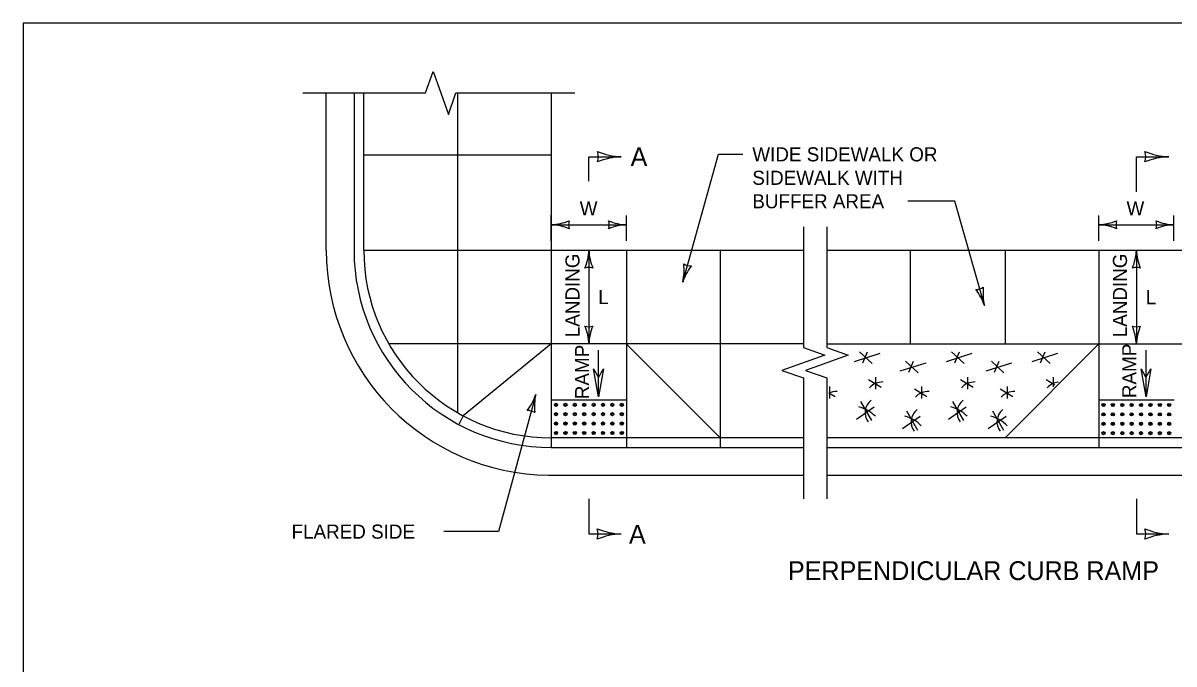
# Model space of a CAD drawing. Extents: x 49991.4 to 50021, y 49987.6 to 50011.4.
# Drawn here: x 50000.336 to 50005.241, y 50008.532 to 50011.263 of the extents above; entities that cross this region are included whole.
import ezdxf

# ---------------------------------------------------------------- set-up
doc = ezdxf.new("R2010")
doc.units = 0
for name, color, linetype in [('Level 1', 7, 'Continuous'), ('Level 2', 7, 'Continuous'), ('Level 3', 7, 'Continuous'), ('Level 6', 7, 'Continuous')]:
    doc.layers.add(name, color=color, linetype=linetype)

msp = doc.modelspace()

# ---------------------------------------------------------------- linework, layer by layer
at = {"layer": 'Level 1'}
for p, q in [((50001.6282, 50010.295), (50001.6282, 50010.9648)), ((50001.7464, 50010.9648), (50001.7464, 50010.2948)), ((50001.7878, 50010.2948), (50001.7878, 50010.9648)), ((50002.1877, 50010.9648), (50002.1877, 50009.6025)), ((50002.587, 50010.9648), (50002.587, 50009.4542)), ((50002.587, 50010.6998), (50001.7878, 50010.6997)), ((50001.7878, 50010.2949), (50003.6615, 50010.2949)), ((50002.9074, 50010.2949), (50002.9075, 50009.4542)), ((50003.3067, 50010.2949), (50003.3066, 50009.4542)), ((50003.7611, 50010.2949), (50007.0343, 50010.2946)), ((50004.1159, 50010.2948), (50004.116, 50009.8954)), ((50004.521, 50010.2948), (50004.5209, 50009.8954)), ((50004.9203, 50010.2948), (50004.9203, 50009.4542)), ((50003.6615, 50009.8954), (50001.8948, 50009.8954)), ((50002.587, 50009.8954), (50002.212, 50009.589)), ((50002.9075, 50009.8952), (50003.3066, 50009.4956)), ((50003.7611, 50009.8955), (50007.0343, 50009.8953)), ((50004.5207, 50009.4956), (50004.9203, 50009.8954)), ((50003.8786, 50009.821), (50003.9881, 50009.8556)), ((50003.9546, 50009.8129), (50003.9008, 50009.8616)), ((50003.9144, 50009.815), (50003.9345, 50009.8616)), ((50004.1504, 50009.7729), (50004.0967, 50009.8216)), ((50004.1102, 50009.775), (50004.1303, 50009.8216)), ((50004.2706, 50009.821), (50004.3801, 50009.8556)), ((50004.3466, 50009.8129), (50004.2928, 50009.8616)), ((50004.3064, 50009.815), (50004.3265, 50009.8616)), ((50004.5162, 50009.7729), (50004.4624, 50009.8216)), ((50004.4759, 50009.775), (50004.4961, 50009.8216)), ((50004.6363, 50009.821), (50004.7459, 50009.8556)), ((50004.7124, 50009.8129), (50004.6586, 50009.8616)), ((50004.6721, 50009.815), (50004.6923, 50009.8616)), ((50004.0744, 50009.781), (50004.1839, 50009.8156)), ((50004.4401, 50009.781), (50004.5497, 50009.8156)), ((50003.9387, 50009.7437), (50003.9923, 50009.7112)), ((50003.9699, 50009.7031), (50003.9699, 50009.7539)), ((50004.3307, 50009.7437), (50004.3843, 50009.7112)), ((50004.3619, 50009.7031), (50004.3619, 50009.7539)), ((50004.6965, 50009.7437), (50004.7329, 50009.7216)), ((50004.7276, 50009.7131), (50004.7276, 50009.7539)), ((50003.7697, 50009.6873), (50003.7961, 50009.6712)), ((50003.7737, 50009.6631), (50003.7737, 50009.7139)), ((50004.1345, 50009.7037), (50004.1881, 50009.6712)), ((50004.1657, 50009.6631), (50004.1657, 50009.7139)), ((50004.5003, 50009.7037), (50004.5539, 50009.6712)), ((50004.5315, 50009.6631), (50004.5315, 50009.7139)), ((50002.9075, 50009.6556), (50002.587, 50009.6556)), ((50003.8875, 50009.575), (50003.9635, 50009.6278)), ((50003.9053, 50009.6501), (50003.9523, 50009.5688)), ((50004.2795, 50009.575), (50004.3555, 50009.6278)), ((50004.2973, 50009.6501), (50004.3443, 50009.5688)), ((50005.2408, 50009.6556), (50004.9203, 50009.6556)), ((50002.212, 50009.589), (50002.1927, 50009.5526)), ((50004.0833, 50009.535), (50004.1594, 50009.5878)), ((50004.1011, 50009.6101), (50004.1481, 50009.5288)), ((50004.4491, 50009.535), (50004.5251, 50009.5878)), ((50004.4669, 50009.6101), (50004.5139, 50009.5288)), ((50003.6615, 50009.4956), (50002.587, 50009.4956)), ((50007.0343, 50009.4956), (50003.7611, 50009.4956)), ((50002.587, 50009.4542), (50003.6615, 50009.4542)), ((50003.7611, 50009.4542), (50007.0343, 50009.4542)), ((50002.575, 50009.336), (50003.6615, 50009.336)), ((50003.7611, 50009.336), (50007.0343, 50009.3357))]:
    msp.add_line(p, q, dxfattribs=at)
msp.add_lwpolyline([(50008.6146, 50011.2628), (50000.3356, 50011.2628), (50000.3356, 50000.0624), (50008.6146, 50000.0624)], close=True, dxfattribs=at)
for centre, radius in [((50002.6073, 50009.6363), 0.00675), ((50002.6073, 50009.6363), 0.00375), ((50002.6473, 50009.6363), 0.00675), ((50002.6473, 50009.6363), 0.00375), ((50002.6873, 50009.6363), 0.00675), ((50002.6873, 50009.6363), 0.00375), ((50002.7273, 50009.6363), 0.00675), ((50002.7273, 50009.6363), 0.00375), ((50002.7673, 50009.6363), 0.00675), ((50002.7673, 50009.6363), 0.00375), ((50002.8073, 50009.6363), 0.00675), ((50002.8073, 50009.6363), 0.00375), ((50002.8473, 50009.6363), 0.00675), ((50002.8473, 50009.6363), 0.00375), ((50002.8873, 50009.6363), 0.00675), ((50002.8873, 50009.6363), 0.00375), ((50004.9403, 50009.6355), 0.00675), ((50004.9403, 50009.6355), 0.00375), ((50004.9803, 50009.6355), 0.00675), ((50004.9803, 50009.6355), 0.00375), ((50005.0203, 50009.6355), 0.00675), ((50005.0203, 50009.6355), 0.00375), ((50005.0603, 50009.6355), 0.00675), ((50005.0603, 50009.6355), 0.00375), ((50005.1003, 50009.6355), 0.00675), ((50005.1003, 50009.6355), 0.00375), ((50005.1403, 50009.6355), 0.00675), ((50005.1403, 50009.6355), 0.00375), ((50005.1803, 50009.6355), 0.00675), ((50005.1803, 50009.6355), 0.00375), ((50005.2203, 50009.6355), 0.00675), ((50005.2203, 50009.6355), 0.00375), ((50002.6073, 50009.5963), 0.00675), ((50002.6073, 50009.5963), 0.00375), ((50002.6473, 50009.5963), 0.00675), ((50002.6473, 50009.5963), 0.00375), ((50002.6873, 50009.5963), 0.00675), ((50002.6873, 50009.5963), 0.00375), ((50002.7273, 50009.5963), 0.00675), ((50002.7273, 50009.5963), 0.00375), ((50002.7673, 50009.5963), 0.00675), ((50002.7673, 50009.5963), 0.00375), ((50002.8073, 50009.5963), 0.00675), ((50002.8073, 50009.5963), 0.00375), ((50002.8473, 50009.5963), 0.00675), ((50002.8473, 50009.5963), 0.00375), ((50002.8873, 50009.5963), 0.00675), ((50002.8873, 50009.5963), 0.00375), ((50004.9403, 50009.5955), 0.00675), ((50004.9403, 50009.5955), 0.00375), ((50004.9803, 50009.5955), 0.00675), ((50004.9803, 50009.5955), 0.00375), ((50005.0203, 50009.5955), 0.00675), ((50005.0203, 50009.5955), 0.00375), ((50005.0603, 50009.5955), 0.00675), ((50005.0603, 50009.5955), 0.00375), ((50005.1003, 50009.5955), 0.00675), ((50005.1003, 50009.5955), 0.00375), ((50005.1403, 50009.5955), 0.00675), ((50005.1403, 50009.5955), 0.00375), ((50005.1803, 50009.5955), 0.00675), ((50005.1803, 50009.5955), 0.00375), ((50005.2203, 50009.5955), 0.00675), ((50005.2203, 50009.5955), 0.00375), ((50002.6073, 50009.5563), 0.00675), ((50002.6073, 50009.5563), 0.00375), ((50002.6473, 50009.5563), 0.00675), ((50002.6473, 50009.5563), 0.00375), ((50002.6873, 50009.5563), 0.00675), ((50002.6873, 50009.5563), 0.00375), ((50002.7273, 50009.5563), 0.00675), ((50002.7273, 50009.5563), 0.00375), ((50002.7673, 50009.5563), 0.00675), ((50002.7673, 50009.5563), 0.00375), ((50002.8073, 50009.5563), 0.00675), ((50002.8073, 50009.5563), 0.00375), ((50002.8473, 50009.5563), 0.00675), ((50002.8473, 50009.5563), 0.00375), ((50002.8873, 50009.5563), 0.00675), ((50002.8873, 50009.5563), 0.00375), ((50004.9403, 50009.5555), 0.00675), ((50004.9403, 50009.5555), 0.00375), ((50004.9803, 50009.5555), 0.00675), ((50004.9803, 50009.5555), 0.00375), ((50005.0203, 50009.5555), 0.00675), ((50005.0203, 50009.5555), 0.00375), ((50005.0603, 50009.5555), 0.00675), ((50005.0603, 50009.5555), 0.00375), ((50005.1003, 50009.5555), 0.00675), ((50005.1003, 50009.5555), 0.00375), ((50005.1403, 50009.5555), 0.00675), ((50005.1403, 50009.5555), 0.00375), ((50005.1803, 50009.5555), 0.00675), ((50005.1803, 50009.5555), 0.00375), ((50005.2203, 50009.5555), 0.00675), ((50005.2203, 50009.5555), 0.00375), ((50002.6073, 50009.5163), 0.00675), ((50002.6073, 50009.5163), 0.00375), ((50002.6473, 50009.5163), 0.00675), ((50002.6473, 50009.5163), 0.00375), ((50002.6873, 50009.5163), 0.00675), ((50002.6873, 50009.5163), 0.00375), ((50002.7273, 50009.5163), 0.00675), ((50002.7273, 50009.5163), 0.00375), ((50002.7673, 50009.5163), 0.00675), ((50002.7673, 50009.5163), 0.00375), ((50002.8073, 50009.5163), 0.00675), ((50002.8073, 50009.5163), 0.00375), ((50002.8473, 50009.5163), 0.00675), ((50002.8473, 50009.5163), 0.00375), ((50002.8873, 50009.5163), 0.00675), ((50002.8873, 50009.5163), 0.00375), ((50004.9403, 50009.5155), 0.00675), ((50004.9403, 50009.5155), 0.00375), ((50004.9803, 50009.5155), 0.00675), ((50004.9803, 50009.5155), 0.00375), ((50005.0203, 50009.5155), 0.00675), ((50005.0203, 50009.5155), 0.00375), ((50005.0603, 50009.5155), 0.00675), ((50005.0603, 50009.5155), 0.00375), ((50005.1003, 50009.5155), 0.00675), ((50005.1003, 50009.5155), 0.00375), ((50005.1403, 50009.5155), 0.00675), ((50005.1403, 50009.5155), 0.00375), ((50005.1803, 50009.5155), 0.00675), ((50005.1803, 50009.5155), 0.00375), ((50005.2203, 50009.5155), 0.00675), ((50005.2203, 50009.5155), 0.00375)]:
    msp.add_circle(centre, radius, dxfattribs=at)
for centre, radius, start, end in [((50002.587, 50010.2947), 0.9588, 179.9835, 269.2811), ((50002.587, 50010.2948), 0.8406, 180, 270), ((50002.587, 50010.2948), 0.7992, 180, 270)]:
    msp.add_arc(centre, radius, start, end, dxfattribs=at)
for centre, major_axis, start_param, end_param in [((50004.0013, 50009.6641), (-0.0764, 0), 4.712389, 5.577205), ((50004.3933, 50009.6641), (-0.0764, 0), 4.712389, 5.577205), ((50004.7591, 50009.6641), (-0.0764, 0), 4.850702, 5.577205), ((50003.8051, 50009.6241), (-0.0764, 0), 4.712389, 5.191885), ((50004.1971, 50009.6241), (-0.0764, 0), 4.712389, 5.577205), ((50004.5629, 50009.6241), (-0.0764, 0), 4.712389, 5.577205), ((50003.8599, 50009.5017), (0.1432, 0), 0.715682, 1.301104), ((50004.0031, 50009.6034), (-0.0787, 0), 5.450961, 6.875887), ((50004.2519, 50009.5017), (0.1432, 0), 0.715682, 1.301104), ((50004.3951, 50009.6034), (-0.0787, 0), 5.450961, 6.875887), ((50004.0557, 50009.4617), (0.1432, 0), 0.715682, 1.301104), ((50004.1989, 50009.5634), (-0.0787, 0), 5.450961, 6.875887), ((50004.4215, 50009.4617), (0.1432, 0), 0.715682, 1.301104), ((50004.5647, 50009.5634), (-0.0787, 0), 5.450961, 6.875887)]:
    msp.add_ellipse(centre, major_axis=major_axis, ratio=0.909091, start_param=start_param, end_param=end_param, dxfattribs=at)
at = {"layer": 'Level 3'}
for p, q in [((50003.1472, 50010.1589), (50003.2993, 50010.7034)), ((50003.2993, 50010.7034), (50003.4037, 50010.7034)), ((50004.3072, 50010.5034), (50004.1058, 50010.5034)), ((50004.4327, 50010.0591), (50004.3072, 50010.5034)), ((50002.587, 50010.3347), (50002.587, 50010.4437)), ((50002.9074, 50010.3349), (50002.9074, 50010.4434)), ((50004.9203, 50010.3348), (50004.9203, 50010.4434)), ((50005.2407, 50010.3348), (50005.2407, 50010.4434)), ((50002.587, 50010.4034), (50002.9074, 50010.4034)), ((50004.9203, 50010.4034), (50005.2407, 50010.4034)), ((50002.7472, 50010.2949), (50002.7472, 50009.8954)), ((50005.0805, 50010.2948), (50005.0805, 50009.8929)), ((50005.0805, 50010.2948), (50005.0805, 50009.8953)), ((50002.7882, 50009.6702), (50002.7882, 50009.8688)), ((50005.1215, 50009.6702), (50005.1215, 50009.8688)), ((50002.5205, 50009.6807), (50002.3624, 50009.0959)), ((50002.3624, 50009.0959), (50002.1296, 50009.0959))]:
    msp.add_line(p, q, dxfattribs=at)
for points in [[(50002.809, 50009.7893), (50002.7882, 50009.6702), (50002.7669, 50009.7893), (50002.788, 50009.753)], [(50005.1423, 50009.7893), (50005.1215, 50009.6702), (50005.1002, 50009.7893), (50005.1213, 50009.753)]]:
    msp.add_lwpolyline(points, close=True, dxfattribs=at)
for centre, radius, start, end in [((50002.5755, 50010.6361), 0.233, 272.8273, 292.0772), ((50002.7152, 50010.4034), 0.0548, 162.1388, 197.8612), ((50002.9166, 50010.6255), 0.2223, 247.456, 267.6395), ((50002.7792, 50010.4034), 0.0548, 342.1388, 17.8612), ((50004.9088, 50010.6361), 0.233, 272.8273, 292.0772), ((50005.0485, 50010.4034), 0.0548, 162.1388, 197.8612), ((50005.2499, 50010.6255), 0.2223, 247.456, 267.6395), ((50005.1125, 50010.4034), 0.0548, 342.1388, 17.8612), ((50002.5778, 50010.1812), 0.2223, 67.456, 87.6395), ((50002.9189, 50010.1706), 0.233, 92.8273, 112.0772), ((50004.9111, 50010.1812), 0.2223, 67.456, 87.6395), ((50005.2522, 50010.1706), 0.233, 92.8273, 112.0772), ((50002.5251, 50010.304), 0.2223, 337.456, 357.6395), ((50002.9799, 50010.3063), 0.233, 182.8273, 202.0772), ((50004.8584, 50010.3039), 0.2223, 337.456, 357.6395), ((50005.3132, 50010.3063), 0.233, 182.8273, 202.0772), ((50002.7472, 50010.1666), 0.0548, 72.1388, 107.8612), ((50002.92, 50010.2105), 0.233, 347.2166, 6.4665), ((50003.3586, 50010.0903), 0.2223, 141.8453, 162.0288), ((50003.1817, 50010.2824), 0.0548, 236.5281, 272.2505), ((50005.0805, 50010.1666), 0.0548, 72.1388, 107.8612), ((50004.3978, 50010.1825), 0.0548, 267.9167, 303.6391), ((50004.2214, 50009.9899), 0.2223, 18.1384, 38.3219), ((50004.6598, 50010.1113), 0.233, 173.7008, 192.9506), ((50002.7472, 50010.0236), 0.0548, 252.1388, 287.8612), ((50002.5145, 50009.8839), 0.233, 2.8273, 22.0772), ((50002.9693, 50009.8862), 0.2223, 157.456, 177.6395), ((50005.0805, 50010.0235), 0.0548, 252.1388, 287.8612), ((50004.8478, 50009.8838), 0.233, 2.8273, 22.0772), ((50005.3026, 50009.8861), 0.2223, 157.456, 177.6395), ((50002.3085, 50009.7475), 0.2223, 322.3228, 342.5063), ((50002.7482, 50009.6311), 0.233, 167.6941, 186.9439), ((50002.4871, 50009.5569), 0.0548, 57.0056, 92.7279)]:
    msp.add_arc(centre, radius, start, end, dxfattribs=at)
at = {"layer": 'Level 6'}
for p, q in [((50002.0512, 50010.9648), (50002.0836, 50011.0562)), ((50002.0836, 50011.0562), (50002.116, 50010.9648)), ((50001.5282, 50010.9648), (50002.0512, 50010.9648)), ((50002.116, 50010.9648), (50002.1484, 50010.8734)), ((50002.1484, 50010.8734), (50002.1808, 50010.9648)), ((50002.1808, 50010.9648), (50002.687, 50010.9648)), ((50002.7472, 50010.5891), (50002.7472, 50010.6934)), ((50002.7472, 50010.6934), (50002.885, 50010.6934)), ((50005.0805, 50010.5434), (50005.0805, 50010.6934)), ((50005.0805, 50010.6934), (50005.2183, 50010.6934)), ((50003.6615, 50010.3949), (50003.6615, 50009.8802)), ((50003.7611, 50010.3949), (50003.7611, 50009.8802)), ((50003.6615, 50009.7506), (50003.6615, 50009.236)), ((50003.7611, 50009.7506), (50003.7611, 50009.236)), ((50002.7475, 50009.236), (50002.7475, 50009.086)), ((50005.0815, 50009.2359), (50005.0815, 50009.0859)), ((50002.7475, 50009.086), (50002.8843, 50009.086)), ((50005.0815, 50009.0859), (50005.2183, 50009.0859))]:
    msp.add_line(p, q, dxfattribs=at)
for points in [[(50003.6615, 50009.8802), (50003.7529, 50009.8478), (50003.5701, 50009.783), (50003.6615, 50009.7506)], [(50003.7611, 50009.8802), (50003.8525, 50009.8478), (50003.6697, 50009.783), (50003.7611, 50009.7506)]]:
    msp.add_lwpolyline(points, dxfattribs=at)
for centre, radius, start, end in [((50002.8972, 50010.9895), 0.2964, 247.456, 267.6395), ((50002.714, 50010.6934), 0.073, 342.1388, 17.8612), ((50005.2305, 50010.9895), 0.2964, 247.456, 267.6395), ((50005.0473, 50010.6934), 0.073, 342.1388, 17.8612), ((50002.9003, 50010.3831), 0.3107, 92.8273, 112.0772), ((50005.2336, 50010.3831), 0.3107, 92.8273, 112.0772), ((50002.8965, 50009.3821), 0.2964, 247.456, 267.6395), ((50002.7133, 50009.086), 0.073, 342.1388, 17.8612), ((50002.8996, 50008.7757), 0.3107, 92.8273, 112.0772), ((50005.2305, 50009.382), 0.2964, 247.456, 267.6395), ((50005.0473, 50009.0859), 0.073, 342.1388, 17.8612), ((50005.2336, 50008.7756), 0.3107, 92.8273, 112.0772)]:
    msp.add_arc(centre, radius, start, end, dxfattribs=at)

# ---------------------------------------------------------------- texts
at = {"layer": 'Level 2'}
for s, height, p in [('A', 0.08, (50002.925, 50010.6534)), ('WIDE SIDEWALK OR', 0.06, (50003.4437, 50010.6734)), ('SIDEWALK WITH', 0.06, (50003.4437, 50010.5734)), ('BUFFER AREA', 0.06, (50003.4437, 50010.4734)), ('W', 0.06, (50002.7081, 50010.4434)), ('W', 0.06, (50005.0385, 50010.4434)), ('L', 0.06, (50002.7872, 50010.0651)), ('L', 0.06, (50005.1205, 50010.065)), ('FLARED SIDE', 0.06, (50001.4801, 50009.0659)), ('A', 0.08, (50002.9181, 50009.0447)), ('PERPENDICULAR CURB RAMP', 0.08, (50003.5955, 50008.8896))]:
    msp.add_text(s, height=height, dxfattribs=at).set_placement(p)
for s, p in [('LANDING', (50002.7072, 50009.9241)), ('LANDING', (50005.0405, 50009.924)), ('RAMP', (50002.7482, 50009.6601)), ('RAMP', (50005.0801, 50009.6647))]:
    msp.add_text(s, height=0.06, rotation=90, dxfattribs=at).set_placement(p)

doc.saveas('drawing.dxf')
